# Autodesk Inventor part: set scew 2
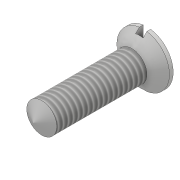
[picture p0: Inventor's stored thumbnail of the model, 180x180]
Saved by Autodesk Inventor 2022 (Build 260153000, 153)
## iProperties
Created: 2016-06
Part Number: set scew 2
Material: Generic
Document SubType Name: Modeling
Designer: CADCIM
Density: 1 g/cm^3
Appearance: Default
Mass: 0.690766 g
Surface Area: 5.88069 cm^2
Volume: 0.690766 cm^3
Author: CADCIM
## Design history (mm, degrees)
sketch "Sketch1"
  geometry: C1 r 3 at (0, 0); 1 further point
  constraints: 1 centre point, 1 coincident
  dimensions: "d0" = 6 diameter of C1
extrude "Extrusion1" new body sketch "Sketch1" distance "d1" = 18; taper "d2" = 0 deg
sketch "Sketch2"
  geometry: L1 (18, -3)-(18, 3) reference; L2 (18, 0)-(18, -3); L3 (18, -3)-(21, -6); L4 (21, -6)-(21, 0); L5 (21, 0)-(18, 0); 1 further point
  constraints: 8 end point, 2 vertical, 1 midpoint, 1 perpendicular
  dimensions: "d4" = 3 distance of L2.start L2.end; "d5" = 6 distance of L4.end L3.end; "d6" = 3 distance from line of L1.start L4
revolve "Revolution1" sketch "Sketch2" stored, may be unused: angle "d7" = 90 deg
sketch "Sketch3"
  geometry: C1 r 5.25 at (0, 0); 1 further point
  constraints: 1 centre point, 1 coincident
  dimensions: "d8" = 10.5 diameter of C1
extrude "Extrusion2" sketch "Sketch3" distance "d9" = 26.75; taper "d10" = 0 deg
sketch "Sketch4"
  geometry: L1 (-0.75, 8.347)-(0.75, 8.347); L2 (0.75, 8.347)-(0.75, -8.125); L3 (0.75, -8.125)-(-0.75, -8.125); L4 (-0.75, -8.125)-(-0.75, 8.347); L5 (0, 0)-(0, 6.165)
  constraints: 10 end point, 3 parallel, 1 horizontal, 1 perpendicular, 1 other
  dimensions: "d11" = 1.5 distance of L1.start L1.end
extrude "Extrusion3" cut sketch "Sketch4" distance "d12" = 1.5; taper "d13" = 0 deg
sketch "Sketch5"
  geometry: L1 (0, 0)-(0, 3); L2 (0, 3)-(-1.732, 0); L3 (-1.732, 0)-(0, 0); L4 (0, 3)-(0, -3) reference; 1 further point
  constraints: 6 end point, 2 midpoint, 1 perpendicular, 1 point on line, 1 vertical
  dimensions: "d21" = 60 deg angle of L2 L3; "d22" = 3 distance of L1.start L1.end
thread "Thread2" dims "d19" = 10, "d20" = 0
revolve "Revolution3" stored, may be unused: angle "d23" = 90 deg
body "Solid1"
